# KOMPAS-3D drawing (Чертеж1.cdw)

Referenced files: Чертеж1.cdw
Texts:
  Корнус Складальне креслення
  Виталий
  Samsung Electronics
  Текст на чертеже
  Размерные надписи
  Шероховатость
  Линия-выноска #1
  Линия-выноска #2
  Линия-выноска #3
  Отклонения формы и база
  Заголовок таблицы
  Ячейка таблицы
  Стрелка вида
  Обозначение изменения
  Фигурная скобка
  Номер узла
  Марка координационной оси
  VRCB
  Выносная надпись
  Обозначение узла
  Марка/позиционное обозначение с линией-выноской
  Марка/позиционное обозначение на линии
  Марка/позиционное обозначение без линии-выноски
  ЭКА-3.01.000
  Фронт апарата.
  Умовна розгортка по диаметру 6028 мм
  Корнус
  Складальне креслення
  Янковий М.Г.
Dimensions and other numbers on the sheet: 03-3604.ДП.СК; 7; 21; 22Х16=352; 4; 2400; 1787; 13527; 780; 6250; 3506; 1№1; 11; 12; 3№3; 4№4; 3№5; 6№6; 8; 40; 800; 4680; 200; 400; 750; 1440; 650; 2800; 1058; 530; 5260; 736; 260; 240; 1450; 3682; 4103; 1:40; 03-3604.ДП.СК-; 0; 1; 2; 3; 5; 6; 9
